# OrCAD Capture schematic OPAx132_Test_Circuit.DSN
size A; title: OPAx132 High-Speed FET-Input Operational Amplifiers; rev: 1.3; note: Datasheet: SBOS054B   EVM: N/A
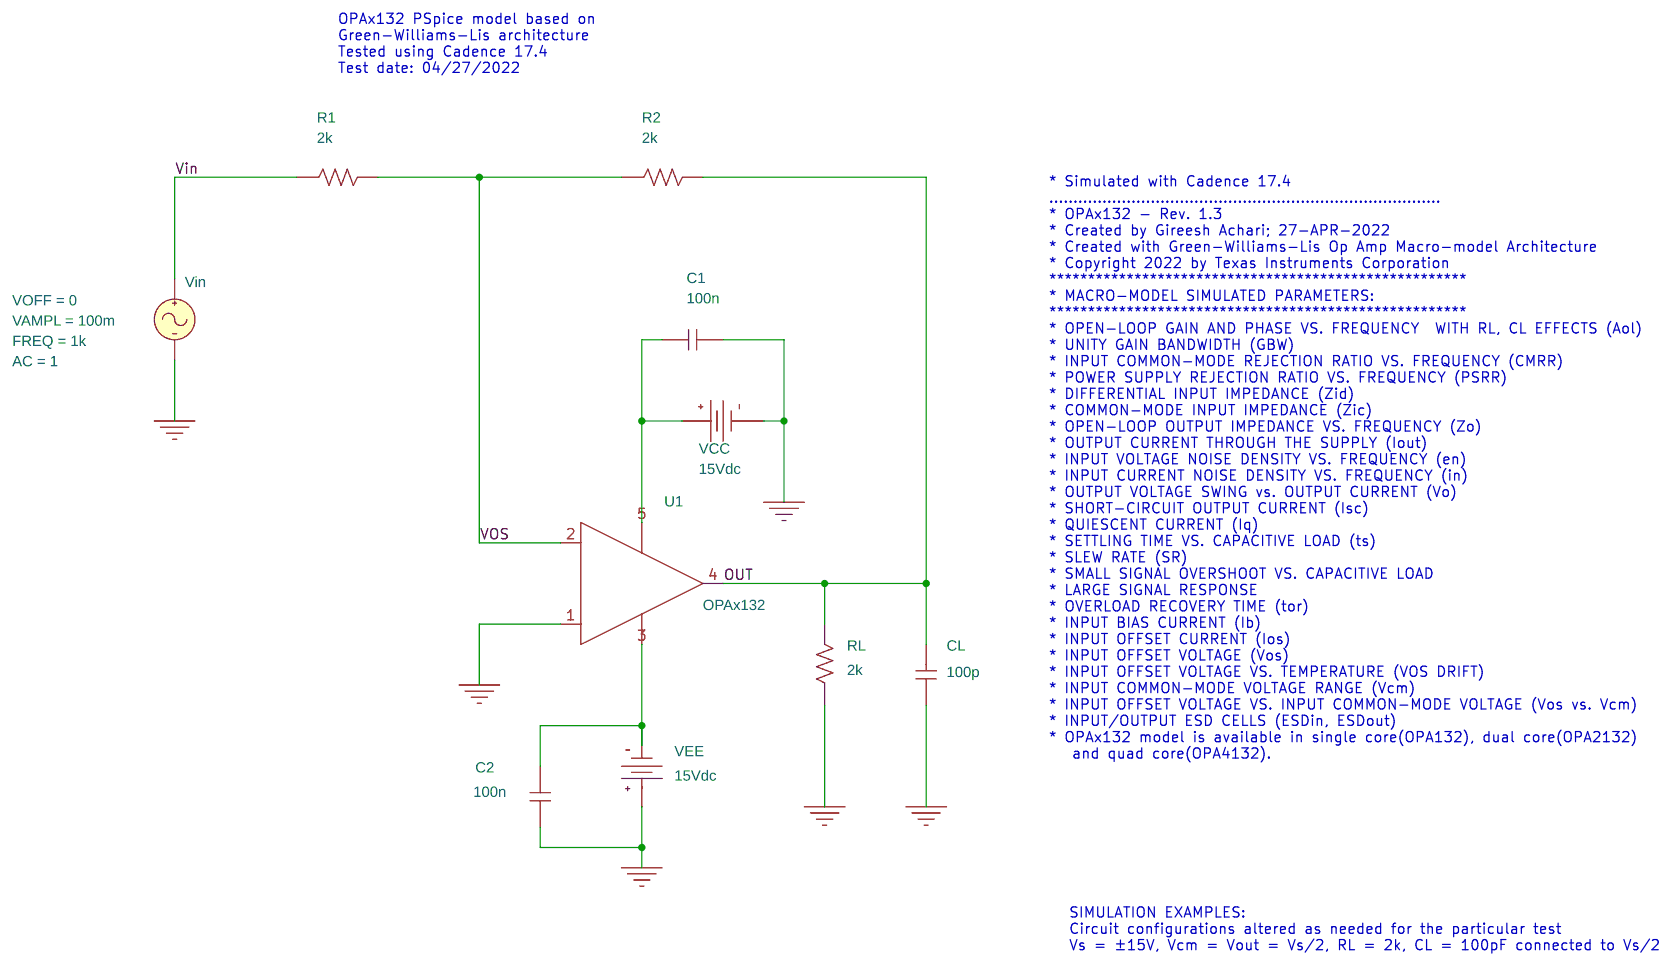
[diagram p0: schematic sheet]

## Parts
C1  100n  [cap196]
C2  100n  [cap196]
CL  100p  [cap196]
R1  2k  [AXRC05]
R2  2k  [AXRC05]
RL  2k  [AXRC05]
U1  OPAx132
VCC  VDC
VEE  VDC
Vin  VSIN

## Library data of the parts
C1 C2 CL = C
R1 R2 RL = R
U1 = OPAx132
VCC VEE = VDC: DC: 15Vdc
Vin = VSIN: AC: 1; FREQ: 1k; VAMPL: 100m; VOFF: 0

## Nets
Vin: R1.1 Vin.1(+)
0: C1.2 C2.1 CL.2 RL.1 U1.1(+) VCC.1(-) VEE.0(+) Vin.2(-)
OUT: CL.1 R2.2 RL.2 U1.4(OUT)
VOS: R1.2 R2.1 U1.2(-)
N27303: C1.1 U1.5(V+) VCC.0(+)
N27354: C2.2 U1.3(V-) VEE.1(-)

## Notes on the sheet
- OPAx132 PSpice model based on
  Green-Williams-Lis architecture
  Tested using Cadence 17.4
  Test date: 04/27/2022
- * Simulated with Cadence 17.4
  .................................................................................
  * OPAx132 - Rev. 1.3
  * Created by Gireesh Achari; 27-APR-2022
  * Created with Green-Williams-Lis Op Amp Macro-model Architecture
  * Copyright 2022 by Texas Instruments Corporation
  ******************************************************
  * MACRO-MODEL SIMULATED PARAMETERS:
  ******************************************************
  * OPEN-LOOP GAIN AND PHASE VS. FREQUENCY  WITH RL, CL EFFECTS (Aol)
  * UNITY GAIN BANDWIDTH (GBW)
  * INPUT COMMON-MODE REJECTION RATIO VS. FREQUENCY (CMRR)
  * POWER SUPPLY REJECTION RATIO VS. FREQUENCY (PSRR)
  * DIFFERENTIAL INPUT IMPEDANCE (Zid)
  * COMMON-MODE INPUT IMPEDANCE (Zic)
  * OPEN-LOOP OUTPUT IMPEDANCE VS. FREQUENCY (Zo)
  * OUTPUT CURRENT THROUGH THE SUPPLY (Iout)
  * INPUT VOLTAGE NOISE DENSITY VS. FREQUENCY (en)
  * INPUT CURRENT NOISE DENSITY VS. FREQUENCY (in)
  * OUTPUT VOLTAGE SWING vs. OUTPUT CURRENT (Vo)
  * SHORT-CIRCUIT OUTPUT CURRENT (Isc)
  * QUIESCENT CURRENT (Iq)
  * SETTLING TIME VS. CAPACITIVE LOAD (ts)
  * SLEW RATE (SR)
  * SMALL SIGNAL OVERSHOOT VS. CAPACITIVE LOAD
  * LARGE SIGNAL RESPONSE
  * OVERLOAD RECOVERY TIME (tor)
  * INPUT BIAS CURRENT (Ib)
  * INPUT OFFSET CURRENT (Ios)
  * INPUT OFFSET VOLTAGE (Vos)
  * INPUT OFFSET VOLTAGE VS. TEMPERATURE (VOS DRIFT)
  * INPUT COMMON-MODE VOLTAGE RANGE (Vcm)
  * INPUT OFFSET VOLTAGE VS. INPUT COMMON-MODE VOLTAGE (Vos vs. Vcm)
  * INPUT/OUTPUT ESD CELLS (ESDin, ESDout)
  * OPAx132 model is available in single core(OPA132), dual core(OPA2132)
     and quad core(OPA4132).
- SIMULATION EXAMPLES:
  Circuit configurations altered as needed for the particular test
  Vs = ±15V, Vcm = Vout = Vs/2, RL = 2k, CL = 100pF connected to Vs/2
